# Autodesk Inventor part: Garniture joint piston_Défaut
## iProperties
Shininess: 64.0
Length Units: 11269
Angle Units: 11279
Time Units: 11290
Mass Units: 11283
Length Display Precision: 3
Angle Display Precision: 2
Compacted: True
Part Number: Garniture joint piston_Défaut
Document SubType Name: Modeling
Created: 2006-01
Material: Par défaut
Designer: riri
Density: 0.0
Volumn: 0.0
Area: 0.0
PropertySet Name: Model Information
Control State: 0
Master: False
Checked Out: False
Author: riri
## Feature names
1. Base1
